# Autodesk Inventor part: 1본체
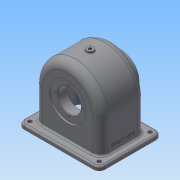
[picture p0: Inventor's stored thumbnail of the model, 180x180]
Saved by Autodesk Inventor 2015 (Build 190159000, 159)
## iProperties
Created: 2022-09
Part Number: 1본체
Material: 일반
Document SubType Name: Modeling
Designer: 학생용
Density: 1 g/cm^3
Appearance: 기본값
Author: 학생용
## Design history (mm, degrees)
sketch "스케치1"
  geometry: L1 (-57, -39)-(57, -39); L2 (57, -39)-(57, 39); L3 (57, 39)-(-57, 39); L4 (-57, 39)-(-57, -39); L5 (-57, -39)-(57, 39); L6 (57, -39)-(-57, 39); 1 further point
  constraints: 12 end point, 2 midpoint, 2 parallel, 1 horizontal, 1 perpendicular
  dimensions: "d0" = 78 distance between parallel lines of L1 L3; "d1" = 114 distance between parallel lines of L4 L2
extrude "돌출1" new body sketch "스케치1" distance "d2" = 121; taper "d3" = 0 deg
fillet "모깎기1" dims "d4" = 57
feature "쉘1" dims "d5" = 5
sketch "스케치2"
  geometry: L1 (70, -54)-(-70, -54); L2 (-70, -54)-(-70, 54); L3 (-70, 54)-(70, 54); L4 (70, 54)-(70, -54); L5 (70, -54)-(-70, 54); L6 (-70, -54)-(70, 54); L7 (-57, -39)-(-57, 39) reference; L8 (-52, -34)-(-52, 34) reference; L9 (52, -34)-(-52, -34); L10 (-52, -34)-(-52, 34); L11 (-52, 34)-(52, 34); L12 (52, 34)-(52, -34); L13 (52, -34)-(-52, 34); L14 (-52, -34)-(52, 34); C1 r 3.3 at (60, 44); C2 r 3.3 at (-60, 44); C3 r 3.3 at (60, -44); C4 r 3.3 at (-60, -44); 1 further point
  constraints: 24 end point, 4 centre point, 4 midpoint, 4 parallel, 3 horizontal, 2 perpendicular, 1 vertical, 6 other
  dimensions: "d6" = 108 distance between parallel lines of L1 L3; "d7" = 140 distance between parallel lines of L4 L2; "d8" = 6.6 diameter of C1; "d9" = 10 distance from line of L3 C1.centre; "d10" = 10 distance from line of L4 C1.centre; "d13" = 120 distance of C1.centre C2.centre; "d16" = 88 distance of C1.centre C3.centre
extrude "돌출2" join sketch "스케치2" distance "d19" = 7; taper "d20" = 0 deg
sketch "스케치3"
  geometry: L1 (70, 64)-(-70, 64) reference; C1 r 31 at (0, 0); 1 further point
  constraints: 1 centre point, 1 vertical alignment
  dimensions: "d21" = 62 diameter of C1; "d22" = 64 distance from line of L1 C1.centre
extrude "돌출3" join sketch "스케치3" distance "d23" = 15; taper "d24" = 0 deg
sketch "스케치4"
  geometry: C1 r 31 at (0, 0) reference; C2 r 20 at (0, 0); 1 further point
  constraints: 1 centre point, 1 coincident
  dimensions: "d25" = 40 diameter of C2
extrude "돌출4" cut sketch "스케치4" distance "d26" = 16; taper "d27" = 0 deg
sketch "스케치5"
  geometry: C1 r 20 at (0, 0) reference; C2 r 17.5 at (0, 0); 1 further point
  constraints: 1 centre point, 1 coincident
  dimensions: "d28" = 35 diameter of C2
extrude "돌출5" cut sketch "스케치5" stored distance "d29" = 16; taper "d30" = 0 deg
node "작업 평면1"
sketch "스케치6"
  geometry: L1 (-52, 64)-(52, 64) reference; C1 r 28 at (0, 0); 2 further points
  constraints: 1 centre point, 1 midpoint, 1 vertical alignment
  dimensions: "d32" = 56 diameter of C1; "d33" = 64 distance from line of L1 C1.centre
extrude "돌출6" join sketch "스케치6" distance "d34" = 14; taper "d35" = 30 deg
sketch "스케치7"
  geometry: L1 (-52, 64)-(-52, 0) reference; L2 (52, 0)-(52, 64) reference; L3 (52, 64)-(70, 64) reference; L4 (70, 64)-(70, 57) reference; L5 (70, 57)-(57, 57) reference; L6 (57, 57)-(57, 0) reference; L7 (-57, 0)-(-57, 57) reference; L8 (-57, 57)-(-70, 57) reference; L9 (-70, 57)-(-70, 64) reference; L10 (-70, 64)-(-52, 64) reference; C1 r 28 at (0, 0) reference; C2 r 20 at (0, 0); A1 r 52 centre (0, 0) between (-52, 0) and (52, 0) reference; A2 r 57 centre (0, 0) between (-57, 0) and (57, 0) reference; 1 further point
  constraints: 1 centre point, 1 coincident
  dimensions: "d36" = 40 diameter of C2
extrude "돌출7" cut sketch "스케치7" distance "d37" = 16; taper "d38" = 0 deg
sketch "스케치8"
  geometry: C1 r 20 at (0, 0) reference; C2 r 32 at (0, 0); 1 further point
  constraints: 1 centre point, 1 coincident
  dimensions: "d39" = 64 diameter of C2
extrude "돌출8" cut sketch "스케치8" stored distance "d40" = 16; taper "d41" = 0 deg
node "작업 평면2"
sketch "스케치9"
  geometry: C1 r 6 at (0, 0); 1 further point
  constraints: 1 centre point, 1 coincident
  dimensions: "d43" = 12 diameter of C1
extrude "돌출9" join sketch "스케치9" stored distance "d44" = 0; taper "d45" = 0 deg
fillet "모깎기2" dims "d46" = 14, "d47" = 9, "d48" = 0.6, "d49" = 1, "d50" = 3
fillet "모깎기3" dims "d51" = 10, "d86" = 3
chamfer "모따기1" distance "d52" = 1; stored, may be unused: second distance "d53" = 2, angle "d54" = 45 deg
sketch "스케치10" dims "d55" = 48
  geometry: C1 r 32 at (0, 0) reference; 6 further points
  constraints: 2 vertical alignment, 1 coincident, 7 other
  dimensions: "d58" = 360 deg dimension on C1.centre point (0, 24) (derived)
hole "구멍1" sketch "스케치10" at (0, 24), (-24, 0), (0, -24), (24, 0) diameter "d60" = 2.459; stored, may be unused: countersink angle "d64" = 90 deg, drill point angle "d66" = 118 deg; dims "d61" = 7, "d62" = 4, "d63" = 2, "d65" = 9
sketch "스케치11" dims "d67" = 48
  geometry: C1 r 31 at (0, 0) reference; 6 further points
  constraints: 2 vertical alignment, 1 coincident, 7 other
  dimensions: "d70" = 360 deg dimension on C1.centre point (0, -24) (derived)
hole "구멍2" sketch "스케치11" at (0, -24), (24, 0), (0, 24), (-24, 0) diameter "d72" = 2.459; stored, may be unused: countersink angle "d76" = 90 deg, drill point angle "d78" = 118 deg; dims "d73" = 7, "d74" = 4, "d75" = 2, "d77" = 9
sketch "스케치12"
  geometry: 2 further points
  constraints: 1 coincident
hole "구멍3" sketch "스케치12" at (0, 0) diameter "d79" = 5.188; stored, may be unused: countersink angle "d83" = 90 deg, drill point angle "d85" = 118 deg; dims "d80" = 15, "d81" = 4, "d82" = 2, "d84" = 15
sketch "스케치13"
  geometry: L1 (64, -19)-(64, 69) reference; L2 (0, -14)-(54, -14) reference; 2 further points
  constraints: 1 other
  dimensions: "d87" = 17 distance from line of L1 point (47, 25); "d88" = 39 distance from line of point (47, 25) L2
extrude "돌출10" join sketch "스케치13" distance "d89" = 0.5; taper "d90" = 0 deg
node "솔리드1"
node "투영된 루프1"
node "절단 모서리 투영1"
other parameters: "d31" = 14, "d42" = 124
